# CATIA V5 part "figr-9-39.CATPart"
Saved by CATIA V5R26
Part number: Part1
Bounding box of the stored display mesh (mm): x -40 to 40, y -20 to 191.034, z 0 to 131.022
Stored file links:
  D:\_Deepak\CATIA\CATIA V5-6R2016_Deepak\Resources\Part files\Partfiles\c09_catia_v5_6r2016_prt\figr-9-39.CATPart
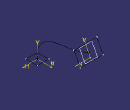
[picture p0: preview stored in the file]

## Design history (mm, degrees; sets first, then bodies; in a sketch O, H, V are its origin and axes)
Set1
  Plane1: type Normal, Curve Sketch2, RefPoint vertex of Sketch2
Body1 (main body)
  Sketch1 on xy-plane, origin (0, 0, 0), H (1, 0, 0), V (0, 1, 0)
    line L1 (20, 20) -> (20, -20)
    line L2 (20, -20) -> (-20, -20)
    line L3 (-20, -20) -> (-20, 20)
    line L4 (-20, 20) -> (20, 20)
    vertical: L1 V, L3 V
    horizontal: L2 H, L4 H
    equidistance: L1 L3 O, L2 L4 O
  Sketch2 on yz-plane, origin (0, 0, 0), H (0, 1, 0), V (0, 0, 1)
    spline S1 through (0, 0) (20, 60) (60, 80) (120, 90) (180, 110)
    point P1 (0, 0)
    coincidence: P1 O
  Sketch3 on Plane1, origin (0, 186.3865, 97.8327), H (1, 0, 0), V (0, -0.4648, 0.8854)
    point P1 (0, 13.7415)
    line L1 (40, 37.4831) -> (40, -10)
    line L2 (40, -10) -> (-40, -10)
    line L3 (-40, -10) -> (-40, 37.4831)
    line L4 (-40, 37.4831) -> (40, 37.4831)
    reference projected point E1 (0, 13.7415) from vertex of Sketch2
    coincidence: P1 V, P1 E1
    vertical: L1 V, L3 V
    horizontal: L2 H, L4 H
    equidistance: L1 L3 P1, L2 L4 P1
